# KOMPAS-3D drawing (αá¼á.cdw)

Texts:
  ПЛК.02.01.01.00 СБ
  Рама сварная
  Ревин ЕЕ
  Noncommercial version
  Лит-Масса-Масштаб
  Материал-Предприятие
  Технические требования
  Раму варить ручной дуговой сваркой по ГОСТ 5264-89 электродами типа Э-46А
  Сварные швы зачисть.
  Базовые поверхности обработать после отжига и рихтовки.
  Неуказанные предельные отклонения размеров: валов h14, отверстий H14,
  остальный  0,5IT14.
  Symbol
  Раму красить серой нитроэмалью (опорные поверхности перед покраской покрыть тонким слоем консистентной смазки)
  Ra25
  ACAD_ISO10W100_RGB_255_64_0_SC_1_THICK_0.15
  ACAD_ISO10W100_RGB_255_128_0_SC_1_THICK_0.15
  ACAD_ISO08W100_RGB_255_64_0_SC_1_THICK_0.15
  ACAD_ISO03W100_RGB_0_0_0_SC_0.3_THICK_0.15
  ACAD_ISO10W100_RGB_255_63_0_SC_1_THICK_0.15
  ACAD_ISO10W100_RGB_255_63_0_SC_0.25_THICK_0.15
  ACAD_ISO10W100_RGB_255_63_0_SC_0.5_THICK_0.15
  gost6_RGB_255_128_0_SC_1_THICK_0.15
  ACAD_ISO10W100_RGB_51_51_51_SC_1_THICK_0.18
  ACAD_ISO10W100_RGB_0_0_0_SC_1_THICK_0.18
  gost6_RGB_255_128_0_SC_0.5_THICK_0.15
  ACAD_ISO10W100_RGB_51_51_51_SC_0.1_THICK_0.25
  ACAD_ISO10W100_RGB_255_128_0_SC_0.5_THICK_0.15
  POLYLINE_STYLE_0.18_RGB_0_0_255
  ACAD_ISO10W100_RGB_255_128_0_SC_0.75_THICK_0.15
  ACAD_ISO03W100_RGB_0_0_255_SC_0.25_THICK_0.5
  ACAD_ISO03W100_RGB_0_0_0_SC_0.1_THICK_0.15
  ACAD_ISO10W100_RGB_255_128_0_SC_1_THICK_0.18
  ACAD_ISO10W100_RGB_51_51_51_SC_1_THICK_0.25
  ACAD_ISO10W100_RGB_0_0_255_SC_0.5_THICK_0.15
  СONTINUOUS_RGB_0_0_0_THICK_0.5
  ACAD_ISO10W100_RGB_255_128_0_SC_0.25_THICK_0.15
  ACAD_ISO10W100_RGB_255_64_0_SC_1_THICK_0.18
  Стили документа
  Подшипник 36207K ГОСТ 831-75
  Подшипник
  ГОСТ
  Подшипник 7212А ГОСТ 27365-87
  Подшипник207 ГОСТ 8338-75
  Подшипник209 ГОСТ 8338-75
  Манжета
  Шайба 8 Л БрКМц3-1 ГОСТ 6402-70
  Шайба пружинная
  Шайба
  БрКМц3-1
  БрКМц3-1 ГОСТ 18175-78
  Болт М8-6g x 22.109.30ХГСА ГОСТ 7808-70
  Болт
  .30ХГСА
  Сталь 30ХГСА ГОСТ 4543-71
  Вавилин В.В
  ПЛК.5.00.00 СБ-
Dimensions and other numbers on the sheet: 50; 850; 950; 23; 529; 587; 370; 416; 4; 3; 30; 125; 202; 2; 1; 2№2; 140; 8№1; 145; 238; 5; 6№1; 192; 8№5; 6; 8№4; 105; 0,05/100; 8; 9; 4№3; 3№6; 7; 106; 100; 6№6; 0,05; 70; 55; 029; -6g; 1:2,5; 0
